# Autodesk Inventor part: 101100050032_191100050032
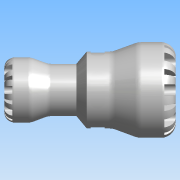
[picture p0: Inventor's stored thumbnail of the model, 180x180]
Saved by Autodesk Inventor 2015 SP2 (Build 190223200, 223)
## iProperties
Created: 2016-12
Part Number: 101100050032_191100050032
Material: PVC-Piping
Description: PLASSON REDUCING COUPLING 50X32 SERIES 1
Document SubType Name: Modeling
Designer: KIM
Mass: 113.204 g
Surface Area: 237.851 cm^2
Volume: 80.8599 cm^3
Density: 1.4 g/cm^3
Appearance: Smooth - White
Author: KIM
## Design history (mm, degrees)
derived "1011.ipt"
feature "Solid1::1011.ipt"
tag "TaggingFeature1"
body "Solid1"
other parameters: "d0" = 152, "d2" = 33.18, "d4" = 85, "d6" = 79, "d7" = 4.16667, "d8" = 58, "d9" = 32, "d11" = 23.1, "d12" = 55, "d13" = 2.66667, "d14" = 68, "d15" = 46.4, "d16" = 20 deg, "d17" = 20 deg, "d18" = 130 deg, "d26" = 0, "d28" = 360 deg, "d30" = 8 deg, "d31" = 1, "d32" = 8 deg, "d33" = 1, "d35" = 0, "d37" = 360 deg, "d39" = 7.2, "d42" = 7.2, "d43" = 0, "d45" = 360 deg, "d47" = 0.64, "d48" = 8 deg, "d49" = 8 deg, "d50" = 0.64, "d52" = 0, "d54" = 360 deg, "d56" = 11.6, "d57" = 17, "d58" = 0.5, "d60" = 10.2, "d61" = 12.5, "d62" = 16.2, "d63" = 0, "d66" = 0, "d68" = 360 deg, "d75" = 9.58673, "d77" = 66.3, "d78" = 0.85, "d1" = 32, "E_" = 85, "H_" = 152, "l_" = 79, "E1" = 58, "l1" = 55, "Plasson" = 1, "d20" = 9, "d21" = 12.5, "d23" = 85, "d40" = 58, "d59" = 19.17345
